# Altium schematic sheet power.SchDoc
size 279 x 215 mm; SheetNumber: 4; SheetTotal: 4
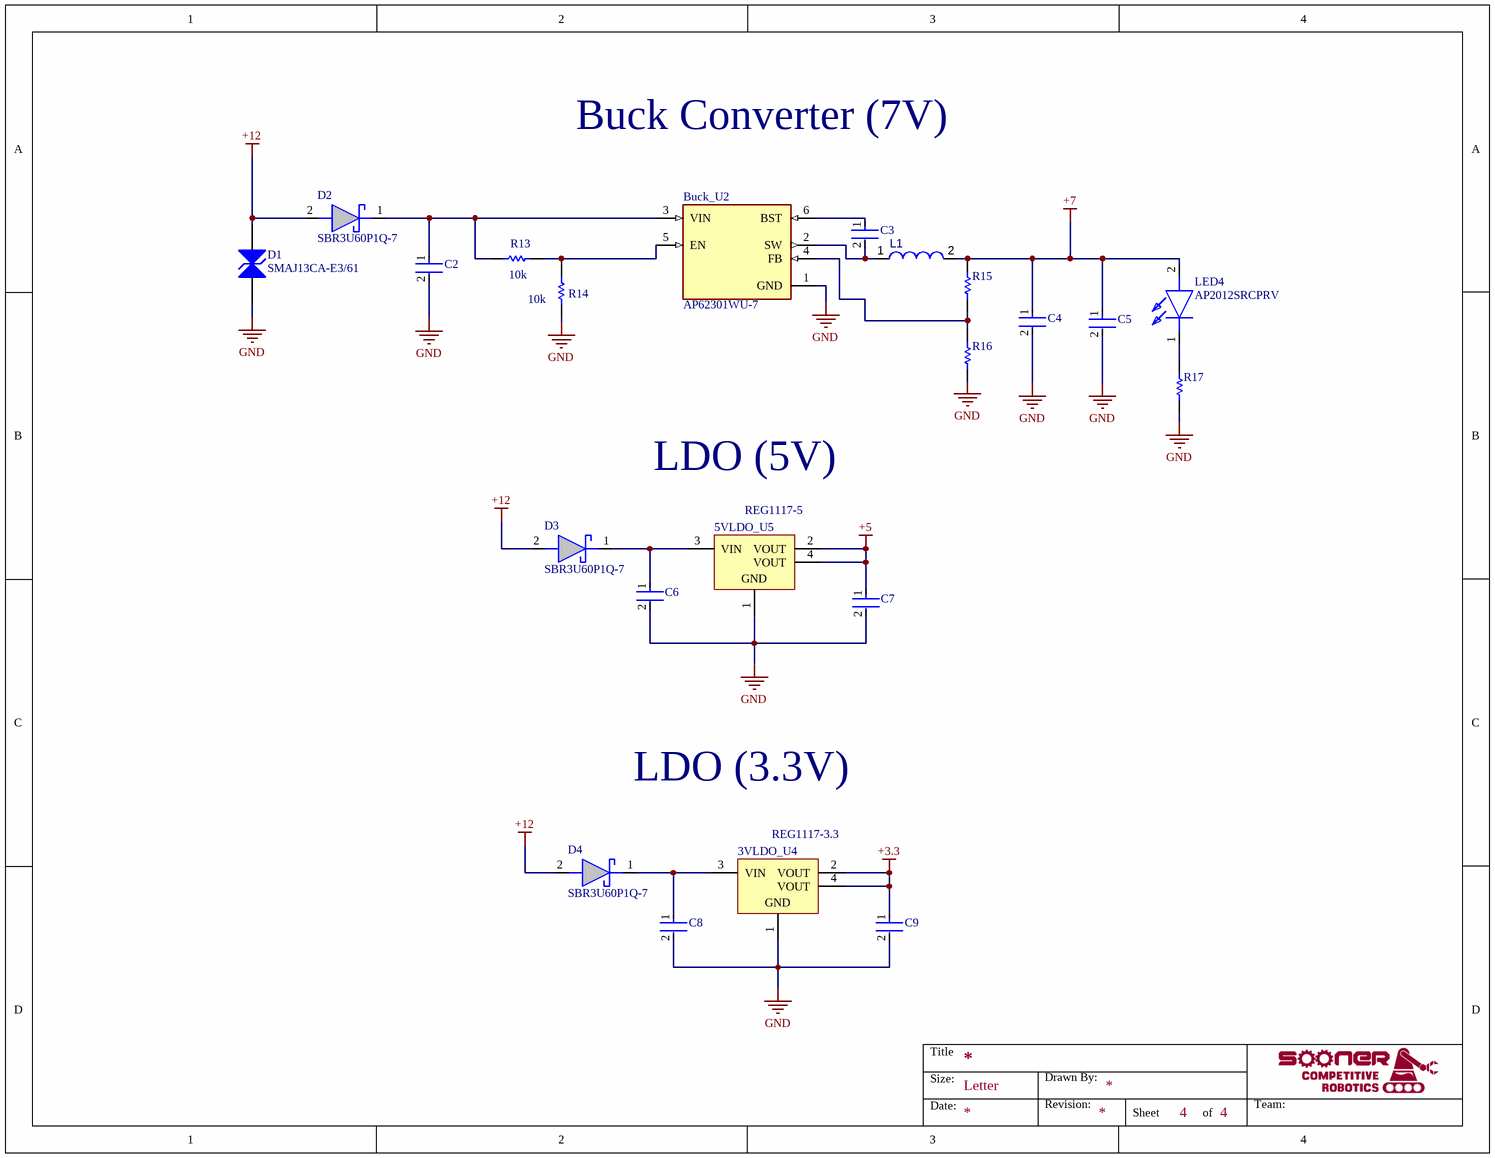
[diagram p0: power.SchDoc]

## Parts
3VLDO_U4  REG1117-3.3  [DCY0004A_M]
5VLDO_U5  REG1117-5  [DCY0004A_M]
Buck_U2  AP62301WU-7  [SOT95P280X100-6N]
C2  GENERIC CAPACITOR  [FP-C0805C-DG-IPC_C]  (value not drawn)
C3  GENERIC CAPACITOR  [FP-C0805C-DG-IPC_C]  (value not drawn)
C4  GENERIC CAPACITOR  [FP-C0805C-DG-IPC_C]  (value not drawn)
C5  GENERIC CAPACITOR  [FP-C0805C-DG-IPC_C]  (value not drawn)
C6  GENERIC CAPACITOR  [FP-C0805C-DG-IPC_C]  (value not drawn)
C7  GENERIC CAPACITOR  [FP-C0805C-DG-IPC_C]  (value not drawn)
C8  GENERIC CAPACITOR  [FP-C0805C-DG-IPC_C]  (value not drawn)
C9  GENERIC CAPACITOR  [FP-C0805C-DG-IPC_C]  (value not drawn)
D1  SMAJ13CA-E3/61  [VISH-DO-214AC-2_N]
D2  SBR3U60P1Q-7  [SBR3U60P1Q7]
D3  SBR3U60P1Q-7  [SBR3U60P1Q7]
D4  SBR3U60P1Q-7  [SBR3U60P1Q7]
L1  RLB0913  [New footprint 1]  (value not drawn)
LED4  AP2012SRCPRV  [LEDC2012X110N]
R13  RES 0805  [RESC2013X50X30ML20T20]  (value not drawn)
R14  RES 0805  [RESC2013X50X30ML20T20]  (value not drawn)
R15  RES 0805  [RESC2013X50X30ML20T20]  (value not drawn)
R16  RES 0805  [RESC2013X50X30ML20T20]  (value not drawn)
R17  RES 0805  [RESC2013X50X30ML20T20]  (value not drawn)

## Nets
+3.3: 3VLDO_U4.2(VOUT) 3VLDO_U4.4(VOUT) C9.1
+5: 5VLDO_U5.2(VOUT) 5VLDO_U5.4(VOUT) C7.1
+7: C4.1 C5.1 L1.2 LED4.2(A) R15.2
+12: D1.1(A1) D2.2(A) D3.2(A) D4.2(A)
GND: 3VLDO_U4.1(GND) 5VLDO_U5.1(GND) Buck_U2.1(GND) C2.2 C4.2 C5.2 C6.2 C7.2 C8.2 C9.2 D1.2(A2) R14.1 R16.1 R17.1
Net3VLDO_U4_3: 3VLDO_U4.3(VIN) C8.1 D4.1(K)
Net5VLDO_U5_3: 5VLDO_U5.3(VIN) C6.1 D3.1(K)
NetBuck_U2_2: Buck_U2.2(SW) C3.2 L1.1
NetBuck_U2_3: Buck_U2.3(VIN) C2.1 D2.1(K) R13.1
NetBuck_U2_4: Buck_U2.4(FB) R15.1 R16.2
NetBuck_U2_5: Buck_U2.5(EN) R13.2 R14.2
NetBuck_U2_6: Buck_U2.6(BST) C3.1
NetLED4_1: LED4.1(K) R17.2

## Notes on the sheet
- Buck Converter (7V)
- (near R13) 10k
- (near R14) 10k
- LDO (5V)
- LDO (3.3V)

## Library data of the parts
3VLDO_U4 5VLDO_U5 = CMP-019-00049-4: LDO Regulator Pos 3.3V 0.8A 4-Pin(3+Tab) SOT-223 Rail
Buck_U2 = CMP-142-000001-1: Converter, buck, 4.2V to 18V input, 3A low IQ synchronous, DC-DC, TSOT26; MF: Diodes Incorporated
C2-C9 = CMP-001-00083-4: GENERIC CAPACITOR 0805 or 0603(1608)
D1 = CMP-0548-00189-2: Transient Voltage Suppressor, 6.40 to 231 V, 13 V Stand-off Voltage, Bi-Directional, -55 to 155 degC, 2-pin DO-214AC, Pb-Free, Tape and Reel; Manufacturer: Vishay Semiconductor; PPPM (W): 400, 300; VWM (V): 13; ID (uA): 2; IFSM: 40 A; VBR Bi-Directional (V): 6.4 to 231
D2-D4 = CMP-077-000000-3: Schottky Diodes & Rectifiers 3A SBR 60Vrrm 3A 0.62Vf 100Ir; Manufacturer_Name: Diodes Inc.; Geometry.Height: 1mm
L1 = CMP-006-00000-1: RLB0913 Series Radial Lead Inductor; Tolerance: 10%; Core Material: Ferrite; Inductor Application: DC-DC CONVERTER; Self Resonant Frequency: 79MHz
LED4 = CMP-013-000000-2: RED LED; Manufacturer_Name: Kingbright
R13-R17 = CMP-009-00177-3: Surface Mount 0805 Resistor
